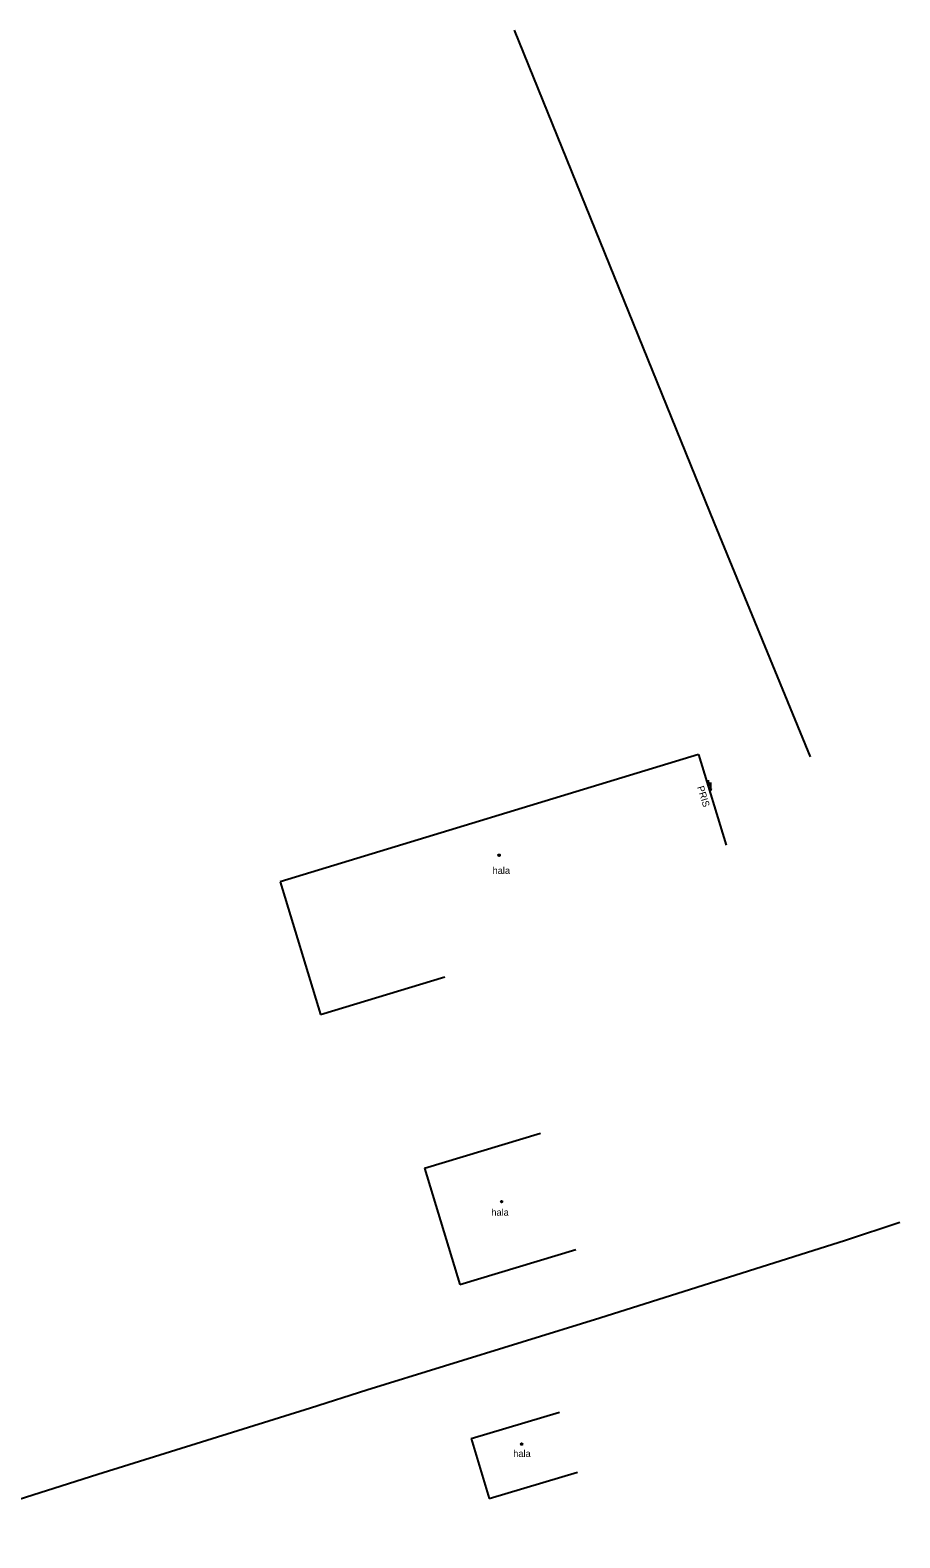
# Model space of a CAD drawing. Extents: x -539244 to -537359, y -1183785 to -1181851.
# Drawn here: x -537977 to -537882.5, y -1182015.3 to -1181851.4 of the extents above; entities that cross this region are included whole.
import ezdxf

# ---------------------------------------------------------------- set-up
doc = ezdxf.new("R2010")
doc.units = 0
for name, color, linetype in [('Vrstva 10', 7, 'Continuous'), ('Vrstva 24', 7, 'Continuous'), ('Vrstva 39', 7, 'Continuous'), ('Vrstva 41', 7, 'Continuous'), ('Vrstva 5', 7, 'Continuous'), ('Vrstva 7', 7, 'Continuous')]:
    doc.layers.add(name, color=color, linetype=linetype)

msp = doc.modelspace()

# ---------------------------------------------------------------- linework, layer by layer
at = {"layer": 'Vrstva 10'}
for p, q in [((-537888.37, -1181982.97), (-537882.48, -1181981.01)), ((-537915.09, -1181991.39), (-537888.37, -1181982.97)), ((-537940.41, -1181999.23), (-537915.09, -1181991.39)), ((-537946.55, -1182001.2), (-537940.41, -1181999.23)), ((-537969.66, -1182008.39), (-537946.55, -1182001.2)), ((-537991.51, -1182015.32), (-537969.66, -1182008.39))]:
    msp.add_line(p, q, dxfattribs=at)
at = {"layer": 'Vrstva 24'}
for p, q in [((-537903.32, -1181932.954), (-537903.32, -1181933.581)), ((-537903.32, -1181933.581), (-537903.07, -1181933.205)), ((-537903.07, -1181933.205), (-537903.07, -1181934.08)), ((-537903.179, -1181933.835), (-537903.07, -1181934.08)), ((-537903.07, -1181934.08), (-537902.959, -1181933.835))]:
    msp.add_line(p, q, dxfattribs=at)
at = {"layer": 'Vrstva 39'}
for centre, radius in [((-537926.039, -1181941.094), 0.09), ((-537926.039, -1181941.094), 0.0398), ((-537925.765, -1181978.773), 0.09), ((-537925.765, -1181978.773), 0.0398), ((-537923.592, -1182005.127), 0.09), ((-537923.592, -1182005.127), 0.0398)]:
    msp.add_circle(centre, radius, dxfattribs=at)
at = {"layer": 'Vrstva 5'}
for p, q in [((-537904.37, -1181930.16), (-537949.84, -1181943.98)), ((-537904.37, -1181930.16), (-537901.374, -1181940.017)), ((-537949.84, -1181943.98), (-537945.47, -1181958.42)), ((-537945.47, -1181958.42), (-537931.931, -1181954.323)), ((-537934.15, -1181975.14), (-537921.554, -1181971.316)), ((-537934.15, -1181975.14), (-537930.31, -1181987.79)), ((-537930.31, -1181987.79), (-537917.714, -1181983.966)), ((-537929.09, -1182004.53), (-537919.484, -1182001.647)), ((-537929.09, -1182004.53), (-537927.13, -1182011.06)), ((-537927.13, -1182011.06), (-537917.524, -1182008.177))]:
    msp.add_line(p, q, dxfattribs=at)
at = {"layer": 'Vrstva 7'}
msp.add_lwpolyline([(-537892.2, -1181930.4), (-537902.64, -1181904.99), (-537924.375, -1181851.39)], dxfattribs=at)

# ---------------------------------------------------------------- texts
at = {"layer": 'Vrstva 41'}
msp.add_text('PRIS', height=0.75, rotation=286.90646, dxfattribs=at).set_placement((-537904.517, -1181933.69))
for p in [(-537926.745, -1181943.135), (-537926.882, -1181980.301), (-537924.503, -1182006.527)]:
    msp.add_text('hala', height=0.75, dxfattribs=at).set_placement(p)

doc.saveas('drawing.dxf')
